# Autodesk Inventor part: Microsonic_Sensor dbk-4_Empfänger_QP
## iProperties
Shininess: 20.0
Length Units: 11269
Angle Units: 11279
Time Units: 11290
Mass Units: 11283
Length Display Precision: 2
Angle Display Precision: 2
Part Number: Microsonic_Sensor dbk-4_Empfänger_QP
Material: Spritzguss
Document SubType Name: Modellieren
Description: dbk-4/Empf/XXX/QP
Checked By: Alves
Created: 2005-08
Designer: Grube
Manufacturer: Standard
Standards Organization: Custom
Density: 0.0
Volumn: 0.0
Area: 0.0
PropertySet Name: Model Information
Control State: 0
Master: False
Checked Out: False
Last Check In By: Tanck
Last Check In Date: 2005-08-10
BESTELLNUMMER: dbk-4/Empf/XXX/QP
ME: ST
Title: dbk-4 Sensoren
Author: Grube
Comments: keine Bemerkung
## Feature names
1. Grundkörper [Extrusion]
2. Verjüngung ,längs [Extrusion]
3. Senkungen [Extrusion]
4. Aussenecken 2mm [Fillet]
5. Radius 1mm Senkungen [Fillet]
6. Bodenausschnitt [Extrusion]
7. Bodenplatte [Extrusion]
8. Füße [Extrusion]
9. Bohrungen 5,2mm [Extrusion]
10. Kabelaustritt [Extrusion]
11. DUO-LED [Revolution]
12. Bohrung1 [Hole]
13. Kabelmantel [Extrusion]
14. Kabellitzen [Extrusion]
15. Gewindeeinsatz [Extrusion]
16. Gewindeeinsatzschlitz [Extrusion]
17. Anordnung Gewindeeinsätze [Rectangular Pattern]
